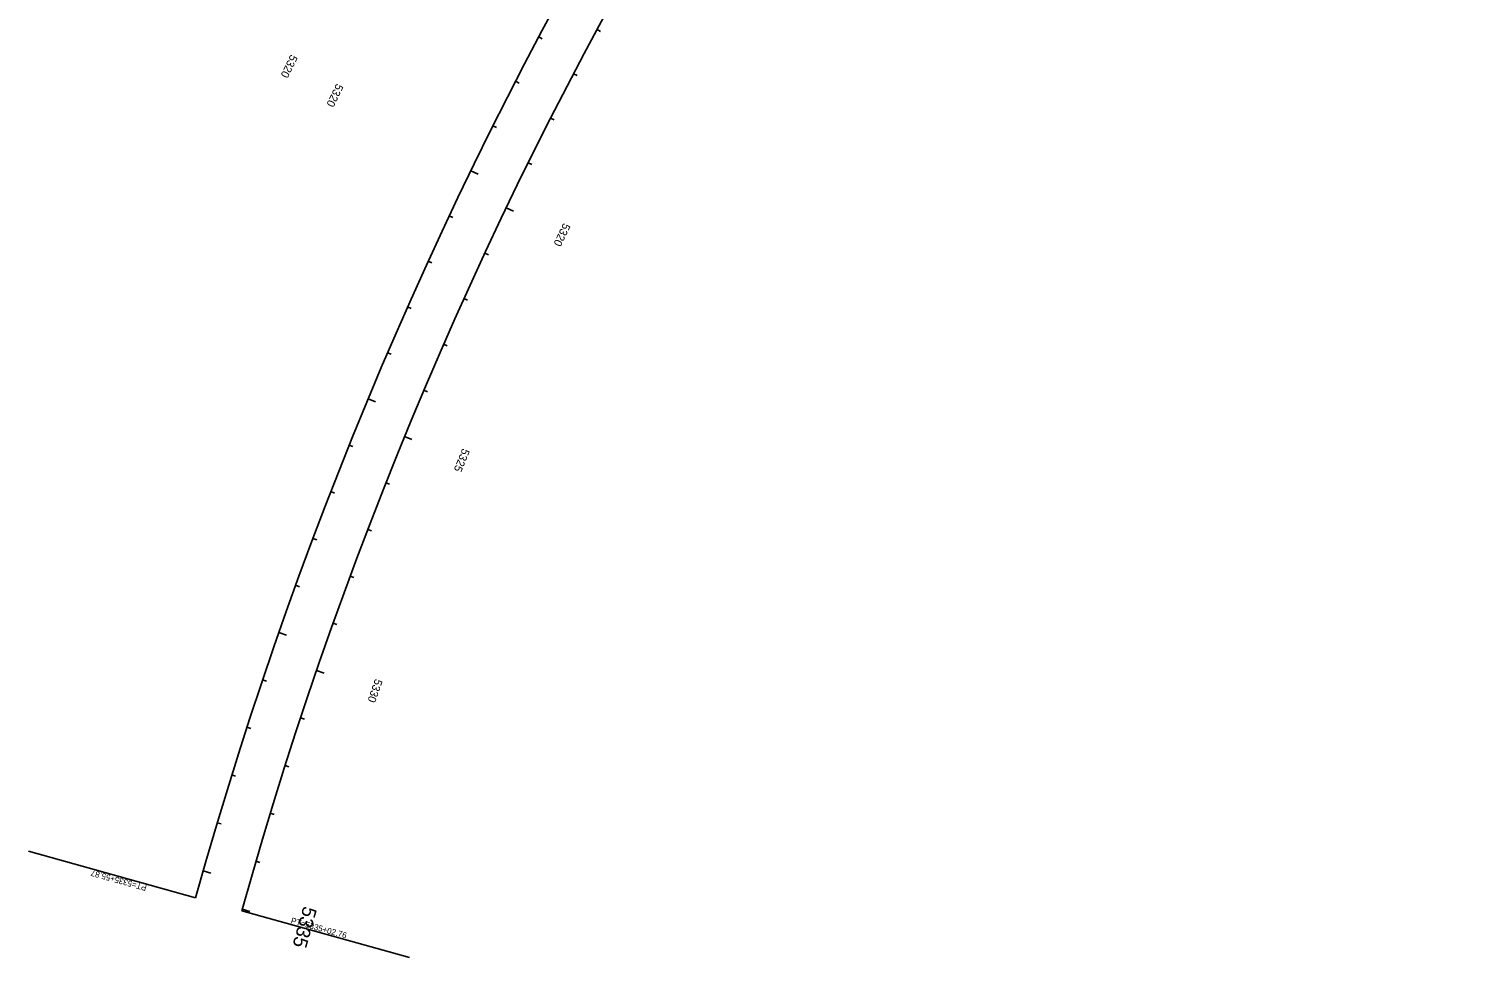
# Model space of a CAD drawing. Extents: x 2160877 to 2175861, y 601747 to 617724.
# Drawn here: x 2160877 to 2163737, y 601747 to 603603 of the extents above; entities that cross this region are included whole.
import ezdxf

# ---------------------------------------------------------------- set-up
doc = ezdxf.new("R2010")
doc.units = 0
for name, color, linetype in [('RD_HC_Cl', 7, 'Continuous'), ('RD_HC_Data', 7, 'Continuous'), ('RD_HC_Data_Tic', 7, 'Continuous'), ('RD_HC_TX_StaOther', 7, 'Continuous')]:
    doc.layers.add(name, color=color, linetype=linetype)

msp = doc.modelspace()

# ---------------------------------------------------------------- linework, layer by layer
at = {"layer": 'RD_HC_Cl'}
for radius in [8641.9, 8545.9]:
    msp.add_arc((2169535, 599544.7), radius, 132.71947, 164.41949, dxfattribs=at)
at = {"layer": 'RD_HC_Data'}
for p, q in [((2161210.6, 601865.9), (2160876.7, 601959)), ((2161303.1, 601840.1), (2161637.9, 601746.8))]:
    msp.add_line(p, q, dxfattribs=at)
at = {"layer": 'RD_HC_Data_Tic'}
for p, q in [((2161896.5, 603586.5), (2161903.6, 603582.8)), ((2162013.2, 603601.2), (2162020.2, 603597.4)), ((2161850.2, 603497.9), (2161857.4, 603494.2)), ((2161966.2, 603512.9), (2161973.3, 603509.2)), ((2161805, 603408.7), (2161812.2, 603405.1)), ((2161920.3, 603424), (2161927.4, 603420.4)), ((2161760.8, 603319), (2161775.2, 603312)), ((2161875.4, 603334.7), (2161882.6, 603331.1)), ((2161831.6, 603244.8), (2161846, 603237.9)), ((2161717.7, 603228.8), (2161724.9, 603225.4)), ((2161788.8, 603154.4), (2161796.1, 603151)), ((2161675.6, 603138.1), (2161682.8, 603134.7)), ((2161747.1, 603063.5), (2161754.4, 603060.2)), ((2161634.5, 603046.9), (2161641.8, 603043.6)), ((2161594.5, 602955.2), (2161601.9, 602952.1)), ((2161706.5, 602972.1), (2161713.8, 602968.9)), ((2161555.6, 602863.1), (2161570.4, 602857)), ((2161666.9, 602880.3), (2161674.3, 602877.2)), ((2161628.4, 602788), (2161643.2, 602781.9)), ((2161517.7, 602770.6), (2161525.1, 602767.6)), ((2161591, 602695.3), (2161598.5, 602692.3)), ((2161480.9, 602677.6), (2161488.4, 602674.7)), ((2161445.2, 602584.2), (2161452.7, 602581.4)), ((2161554.7, 602602.1), (2161562.2, 602599.2)), ((2161410.6, 602490.4), (2161418.1, 602487.6)), ((2161519.5, 602508.5), (2161527, 602505.7)), ((2161485.3, 602414.5), (2161492.9, 602411.8)), ((2161377, 602396.2), (2161392.2, 602390.9)), ((2161452.3, 602320.1), (2161467.4, 602314.9)), ((2161344.6, 602301.6), (2161352.2, 602299)), ((2161313.2, 602206.6), (2161320.9, 602204.2)), ((2161420.4, 602225.4), (2161428, 602222.9)), ((2161389.6, 602130.2), (2161397.2, 602127.8)), ((2161283, 602111.3), (2161290.6, 602108.9)), ((2161359.9, 602034.7), (2161367.5, 602032.4)), ((2161253.9, 602015.6), (2161261.5, 602013.4)), ((2161225.8, 601919.7), (2161241.2, 601915.3)), ((2161331.3, 601938.9), (2161339, 601936.7)), ((2161303.8, 601842.8), (2161319.3, 601838.5))]:
    msp.add_line(p, q, dxfattribs=at)

# ---------------------------------------------------------------- texts
at = {"layer": 'RD_HC_Data'}
for s, rotation, p in [('PT=5335+55.87', 164.4195, (2161113.8, 601890.8)), ('PT=5335+02.76', 344.4195, (2161400, 601815.2))]:
    msp.add_text(s, height=12, rotation=rotation, dxfattribs=at).set_placement(p)
at = {"layer": 'RD_HC_TX_StaOther'}
for s, height, rotation, p in [('5320', 16, 244.0312, (2161400.9, 603552.4)), ('5320', 16, 244.1041, (2161492.4, 603494.2)), ('5320', 16, 244.3443, (2161946.3, 603215.6)), ('5325', 16, 247.6966, (2161744.4, 602765.1)), ('5330', 16, 251.0488, (2161569.6, 602304.5)), ('5335', 28, 254.401, (2161426.5, 601850.6))]:
    msp.add_text(s, height=height, rotation=rotation, dxfattribs=at).set_placement(p)

doc.saveas('drawing.dxf')
